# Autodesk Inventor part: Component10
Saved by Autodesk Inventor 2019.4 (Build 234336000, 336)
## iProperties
Created: 2020-06
Part Number: Component10
Material: Generic
Document SubType Name: Modeling
Designer: Administrator
Density: 1 g/cm^3
Appearance: Default
Title: Component10
Author: Administrator
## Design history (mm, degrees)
